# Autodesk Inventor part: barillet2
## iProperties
Shininess: 64.0
Length Units: 11269
Angle Units: 11279
Time Units: 11290
Mass Units: 11283
Length Display Precision: 3
Angle Display Precision: 2
Compacted: True
Part Number: barillet2
Document SubType Name: Modeling
Created: 2005-01
Material: Par défaut
Designer: Flavien MARTY
Density: 0.0
Volumn: 0.0
Area: 0.0
PropertySet Name: Model Information
Control State: 0
Master: False
Checked Out: False
Norme de conversion: STEP AP203
Nom du fichier: barillet2.STEP
Préprocesseur: SolidWorks 2001039
Postprocesseur: Build: Release: 6 RTM Build: 90b - Date: Tue 09/24/2002
Unités envoyées: MILLIMETERS
Incertitude: 0.0
Author: Flavien MARTY
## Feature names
1. Base1
